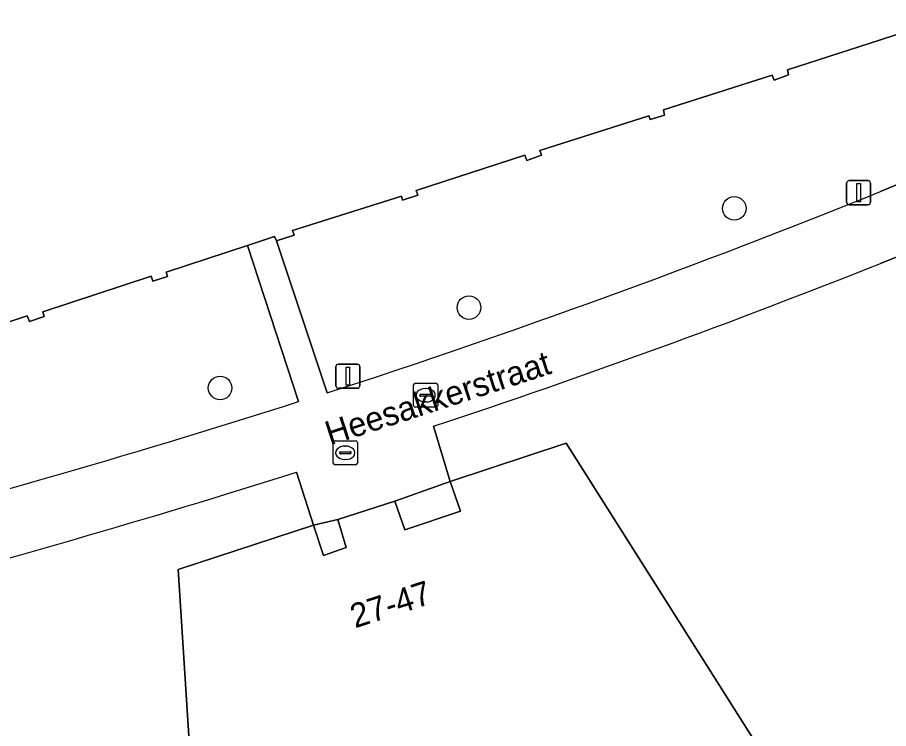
# Model space of a CAD drawing. Extents: x 159262 to 160143, y 383399 to 384319.
# Drawn here: x 159464.14 to 159500.33, y 383959.24 to 383988.77 of the extents above; entities that cross this region are included whole.
import ezdxf

# ---------------------------------------------------------------- set-up
doc = ezdxf.new("R2010")
doc.units = 0
for name, color, linetype in [('IMGEO_Boom', 7, 'Continuous'), ('IMGEO_Brandkraan', 7, 'Continuous'), ('IMGEO_Groenvoorziening', 7, 'Continuous'), ('IMGEO_Kolk', 7, 'Continuous'), ('IMGEO_Lichtmast', 7, 'Continuous'), ('IMGEO_Openbare_ruimte_label', 7, 'Continuous'), ('IMGEO_Pand', 7, 'Continuous'), ('IMGEO_Pand_nummerreeks', 7, 'Continuous'), ('IMGEO_Voetpad_open', 7, 'Continuous')]:
    doc.layers.add(name, color=color, linetype=linetype)

msp = doc.modelspace()

# ---------------------------------------------------------------- linework, layer by layer
at = {"layer": 'IMGEO_Boom'}
for centre in [(159493.922, 383980.836), (159482.9, 383976.718), (159472.56, 383973.38)]:
    msp.add_circle(centre, 0.489, dxfattribs=at)
at = {"layer": 'IMGEO_Brandkraan'}
for p, q in [((159480.6, 383972.654), (159480.6, 383973.506)), ((159480.675, 383973.58), (159481.527, 383973.58)), ((159481.088, 383973.36), (159481.113, 383973.36)), ((159481.601, 383973.506), (159481.601, 383972.654)), ((159480.859, 383973.074), (159480.859, 383973.086)), ((159481.297, 383973.037), (159480.899, 383973.037)), ((159480.902, 383973.123), (159481.3, 383973.123)), ((159481.343, 383973.086), (159481.343, 383973.074)), ((159481.527, 383972.58), (159480.675, 383972.58)), ((159481.111, 383972.8), (159481.086, 383972.8))]:
    msp.add_line(p, q, dxfattribs=at)
for points in [[(159480.6, 383972.654), (159480.6, 383973.506)], [(159480.675, 383973.58), (159481.527, 383973.58)], [(159481.601, 383973.506), (159481.601, 383972.654)], [(159481.527, 383972.58), (159480.675, 383972.58)]]:
    msp.add_lwpolyline(points, dxfattribs=at)
for centre, radius, start, end in [((159480.677, 383973.504), 0.0765, 91.552, 178.448), ((159480.677, 383973.504), 0.0765, 91.552, 178.448), ((159481.525, 383973.504), 0.0765, 1.552, 88.448), ((159481.525, 383973.504), 0.0765, 1.552, 88.448), ((159480.899, 383973.083), 0.0403, 85.8775, 175.7526), ((159480.896, 383973.073), 0.0366, 178.938, 274.7102), ((159481.3, 383973.08), 0.043, 264.8664, 352.4533), ((159481.304, 383973.085), 0.0386, 1.7309, 96.639), ((159480.677, 383972.656), 0.0765, 181.552, 268.448), ((159480.677, 383972.656), 0.0765, 181.552, 268.448), ((159481.525, 383972.656), 0.0765, 271.552, 358.448), ((159481.525, 383972.656), 0.0765, 271.552, 358.448)]:
    msp.add_arc(centre, radius, start, end, dxfattribs=at)
for centre, major_axis, ratio, start_param, end_param in [((159481.087, 383973.08), (-0.387, 0.002), 0.722429, 4.712389, 7.853982), ((159481.112, 383973.08), (-0.39, 0.002), 0.717154, 1.570796, 4.712389)]:
    msp.add_ellipse(centre, major_axis=major_axis, ratio=ratio, start_param=start_param, end_param=end_param, dxfattribs=at)
at = {"layer": 'IMGEO_Groenvoorziening'}
for points in [[(159500.631, 383988.039), (159500, 383987.836), (159496.135, 383986.59), (159496.17, 383986.383), (159495.575, 383986.162), (159495.498, 383986.37), (159490.984, 383984.923), (159491.03, 383984.711), (159490.426, 383984.521), (159490.367, 383984.684), (159485.849, 383983.247), (159485.907, 383983.042), (159485.308, 383982.83), (159485.224, 383983.041), (159480.708, 383981.58), (159480.777, 383981.383), (159480.145, 383981.175), (159480.098, 383981.351), (159475.566, 383979.918), (159475.634, 383979.73), (159474.907, 383979.484), (159477.007, 383973.173)], [(159513.761, 383961.777), (159513.555, 383964.997), (159512.437, 383982.498), (159518.095, 383984.323), (159517.519, 383986.082), (159507.775, 383981.75), (159503.64, 383980.018), (159500, 383978.55)], [(159500, 383981.537), (159506.714, 383984.332)], [(159475.818, 383972.813), (159473.695, 383979.298), (159470.318, 383978.188), (159470.373, 383978.009), (159469.77, 383977.812), (159469.69, 383978.016), (159465.191, 383976.542), (159465.245, 383976.342), (159464.635, 383976.146), (159464.539, 383976.369), (159460.048, 383974.863)], [(159481.431, 383971.787), (159482.115, 383969.493), (159486.934, 383971.093), (159496.316, 383956.284), (159498.045, 383953.561)], [(159472.152, 383945.162), (159471.946, 383948.349), (159470.816, 383965.847), (159476.434, 383967.682), (159475.738, 383969.889)]]:
    msp.add_lwpolyline(points, dxfattribs=at)
for centre, radius, start, end in [((159369.015, 384305.833), 349.75, 287.98501, 291.994), ((159373.892, 384295.928), 341.514, 288.3541, 291.67007), ((159361.701, 384330.59), 375.535, 280.84144, 287.69069), ((159363.187, 384324.991), 372.512, 281.6203, 287.58626)]:
    msp.add_arc(centre, radius, start, end, dxfattribs=at)
at = {"layer": 'IMGEO_Kolk'}
for p, q in [((159477.261, 383970.261), (159477.261, 383971.113)), ((159477.336, 383971.187), (159478.188, 383971.187)), ((159478.262, 383971.113), (159478.262, 383970.261)), ((159477.563, 383970.73), (159477.961, 383970.73)), ((159477.749, 383970.967), (159477.774, 383970.967)), ((159477.52, 383970.681), (159477.52, 383970.693)), ((159477.958, 383970.644), (159477.56, 383970.644)), ((159477.772, 383970.407), (159477.747, 383970.407)), ((159478.004, 383970.693), (159478.004, 383970.681)), ((159478.188, 383970.187), (159477.336, 383970.187))]:
    msp.add_line(p, q, dxfattribs=at)
for points in [[(159477.261, 383970.261), (159477.261, 383971.113)], [(159477.336, 383971.187), (159478.188, 383971.187)], [(159478.262, 383971.113), (159478.262, 383970.261)], [(159478.188, 383970.187), (159477.336, 383970.187)]]:
    msp.add_lwpolyline(points, dxfattribs=at)
for centre, radius, start, end in [((159477.338, 383971.111), 0.0765, 91.552, 178.448), ((159477.338, 383971.111), 0.0765, 91.552, 178.448), ((159478.186, 383971.111), 0.0765, 1.552, 88.448), ((159478.186, 383971.111), 0.0765, 1.552, 88.448), ((159477.56, 383970.69), 0.0403, 85.8775, 175.7526), ((159477.965, 383970.692), 0.0386, 1.7309, 96.639), ((159477.557, 383970.68), 0.0366, 178.938, 274.7102), ((159477.961, 383970.687), 0.043, 264.8664, 352.4533), ((159477.338, 383970.263), 0.0765, 181.552, 268.448), ((159477.338, 383970.263), 0.0765, 181.552, 268.448), ((159478.186, 383970.263), 0.0765, 271.552, 358.448), ((159478.186, 383970.263), 0.0765, 271.552, 358.448)]:
    msp.add_arc(centre, radius, start, end, dxfattribs=at)
for centre, major_axis, ratio, start_param, end_param in [((159477.748, 383970.687), (-0.387, 0.002), 0.722429, 4.712389, 7.853982), ((159477.773, 383970.687), (-0.39, 0.002), 0.717154, 1.570796, 4.712389)]:
    msp.add_ellipse(centre, major_axis=major_axis, ratio=ratio, start_param=start_param, end_param=end_param, dxfattribs=at)
at = {"layer": 'IMGEO_Lichtmast'}
for p, q in [((159498.69, 383981.989), (159499.48, 383981.989)), ((159499.48, 383981.989), (159498.69, 383981.989)), ((159498.59, 383981.089), (159498.59, 383981.889)), ((159498.59, 383981.889), (159498.59, 383981.089)), ((159499.58, 383981.889), (159499.58, 383981.089)), ((159499.58, 383981.089), (159499.58, 383981.889)), ((159499.48, 383980.989), (159498.69, 383980.989)), ((159498.69, 383980.989), (159499.48, 383980.989)), ((159477.473, 383974.369), (159478.263, 383974.369)), ((159478.263, 383974.369), (159477.473, 383974.369)), ((159477.373, 383973.469), (159477.373, 383974.269)), ((159477.373, 383974.269), (159477.373, 383973.469)), ((159478.363, 383974.269), (159478.363, 383973.469)), ((159478.363, 383973.469), (159478.363, 383974.269)), ((159478.263, 383973.369), (159477.473, 383973.369)), ((159477.473, 383973.369), (159478.263, 383973.369))]:
    msp.add_line(p, q, dxfattribs=at)
for points in [[(159499.01, 383981.864), (159499.16, 383981.864), (159499.16, 383981.114), (159499.01, 383981.114), (159499.01, 383981.864)], [(159477.793, 383974.244), (159477.943, 383974.244), (159477.943, 383973.494), (159477.793, 383973.494), (159477.793, 383974.244)]]:
    msp.add_lwpolyline(points, dxfattribs=at)
for centre, start, end in [((159498.69, 383981.889), 90, 180), ((159498.69, 383981.889), 90, 180), ((159499.48, 383981.889), 0, 90), ((159499.48, 383981.889), 360, 90), ((159498.69, 383981.089), 180, 270), ((159498.69, 383981.089), 180, 270), ((159499.48, 383981.089), 270, 0), ((159499.48, 383981.089), 270, 0), ((159477.473, 383974.269), 90, 180), ((159477.473, 383974.269), 90, 180), ((159478.263, 383974.269), 0, 90), ((159478.263, 383974.269), 360, 90), ((159477.473, 383973.469), 180, 270), ((159477.473, 383973.469), 180, 270), ((159478.263, 383973.469), 270, 0), ((159478.263, 383973.469), 270, 0)]:
    msp.add_arc(centre, 0.1, start, end, dxfattribs=at)
at = {"layer": 'IMGEO_Pand'}
msp.add_lwpolyline([(159460.048, 383974.863), (159464.539, 383976.369), (159464.635, 383976.146), (159465.245, 383976.342), (159465.191, 383976.542), (159469.69, 383978.016), (159469.77, 383977.812), (159470.373, 383978.009), (159470.318, 383978.188), (159473.695, 383979.298), (159474.824, 383979.669), (159474.907, 383979.484), (159475.634, 383979.73), (159475.566, 383979.918), (159480.098, 383981.351), (159480.145, 383981.175), (159480.777, 383981.383), (159480.708, 383981.58), (159485.224, 383983.041), (159485.308, 383982.83), (159485.907, 383983.042), (159485.849, 383983.247), (159490.367, 383984.684), (159490.426, 383984.521), (159491.03, 383984.711), (159490.984, 383984.923), (159495.498, 383986.37), (159495.575, 383986.162), (159496.17, 383986.383), (159496.135, 383986.59), (159500, 383987.836), (159500.631, 383988.039)], dxfattribs=at)
msp.add_lwpolyline([(159488.959, 383953.865), (159496.316, 383956.284), (159486.934, 383971.093), (159482.115, 383969.493), (159482.544, 383968.266), (159480.232, 383967.495), (159479.82, 383968.683), (159477.446, 383967.917), (159477.8, 383966.75), (159476.854, 383966.419), (159476.434, 383967.682), (159470.816, 383965.847), (159471.946, 383948.349), (159479.284, 383950.739), (159478.897, 383951.967), (159488.592, 383955.004)], close=True, dxfattribs=at)
at = {"layer": 'IMGEO_Voetpad_open'}
for points in [[(159500, 383978.55), (159503.64, 383980.018), (159507.775, 383981.75), (159517.519, 383986.082), (159518.095, 383984.323), (159518.531, 383983.029), (159519.53, 383983.366), (159519.13, 383984.556), (159521.481, 383985.305), (159521.887, 383984.166), (159524.236, 383985.002), (159523.814, 383986.186), (159522.934, 383988.766)], [(159506.714, 383984.332), (159500, 383981.537)], [(159477.007, 383973.173), (159474.907, 383979.484), (159474.824, 383979.669), (159473.695, 383979.298), (159475.818, 383972.813)], [(159475.738, 383969.889), (159476.434, 383967.682), (159477.446, 383967.917), (159479.82, 383968.683), (159482.115, 383969.493), (159481.431, 383971.787)]]:
    msp.add_lwpolyline(points, dxfattribs=at)
for points in [[(159479.82, 383968.683), (159480.232, 383967.495), (159482.544, 383968.266), (159482.115, 383969.493)], [(159476.434, 383967.682), (159476.854, 383966.419), (159477.8, 383966.75), (159477.446, 383967.917)]]:
    msp.add_lwpolyline(points, close=True, dxfattribs=at)
for centre, radius, start, end in [((159369.015, 384305.833), 349.75, 287.98501, 291.994), ((159373.892, 384295.928), 341.514, 288.3541, 291.67007), ((159361.701, 384330.59), 375.535, 280.84144, 287.69069), ((159363.187, 384324.991), 372.512, 281.6203, 287.58626)]:
    msp.add_arc(centre, radius, start, end, dxfattribs=at)

# ---------------------------------------------------------------- texts
at = {"layer": 'IMGEO_Openbare_ruimte_label'}
msp.add_text('Heesakkerstraat', height=1, rotation=18.0001, dxfattribs=at).set_placement((159477.125, 383970.986))
at = {"layer": 'IMGEO_Pand_nummerreeks'}
msp.add_text('27-47', height=1, rotation=17.9837, dxfattribs=at).set_placement((159478.166, 383963.396))

doc.saveas('drawing.dxf')
